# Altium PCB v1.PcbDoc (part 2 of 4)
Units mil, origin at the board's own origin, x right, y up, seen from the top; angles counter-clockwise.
Board outline 3043 x 5109 mil, 2 copper layers (Top Layer, Bottom Layer), stack 62 mil thick; 379 components, 219 nets, 963 pads, 1099 vias.
Unrouted connection lines stored in the file: 1.
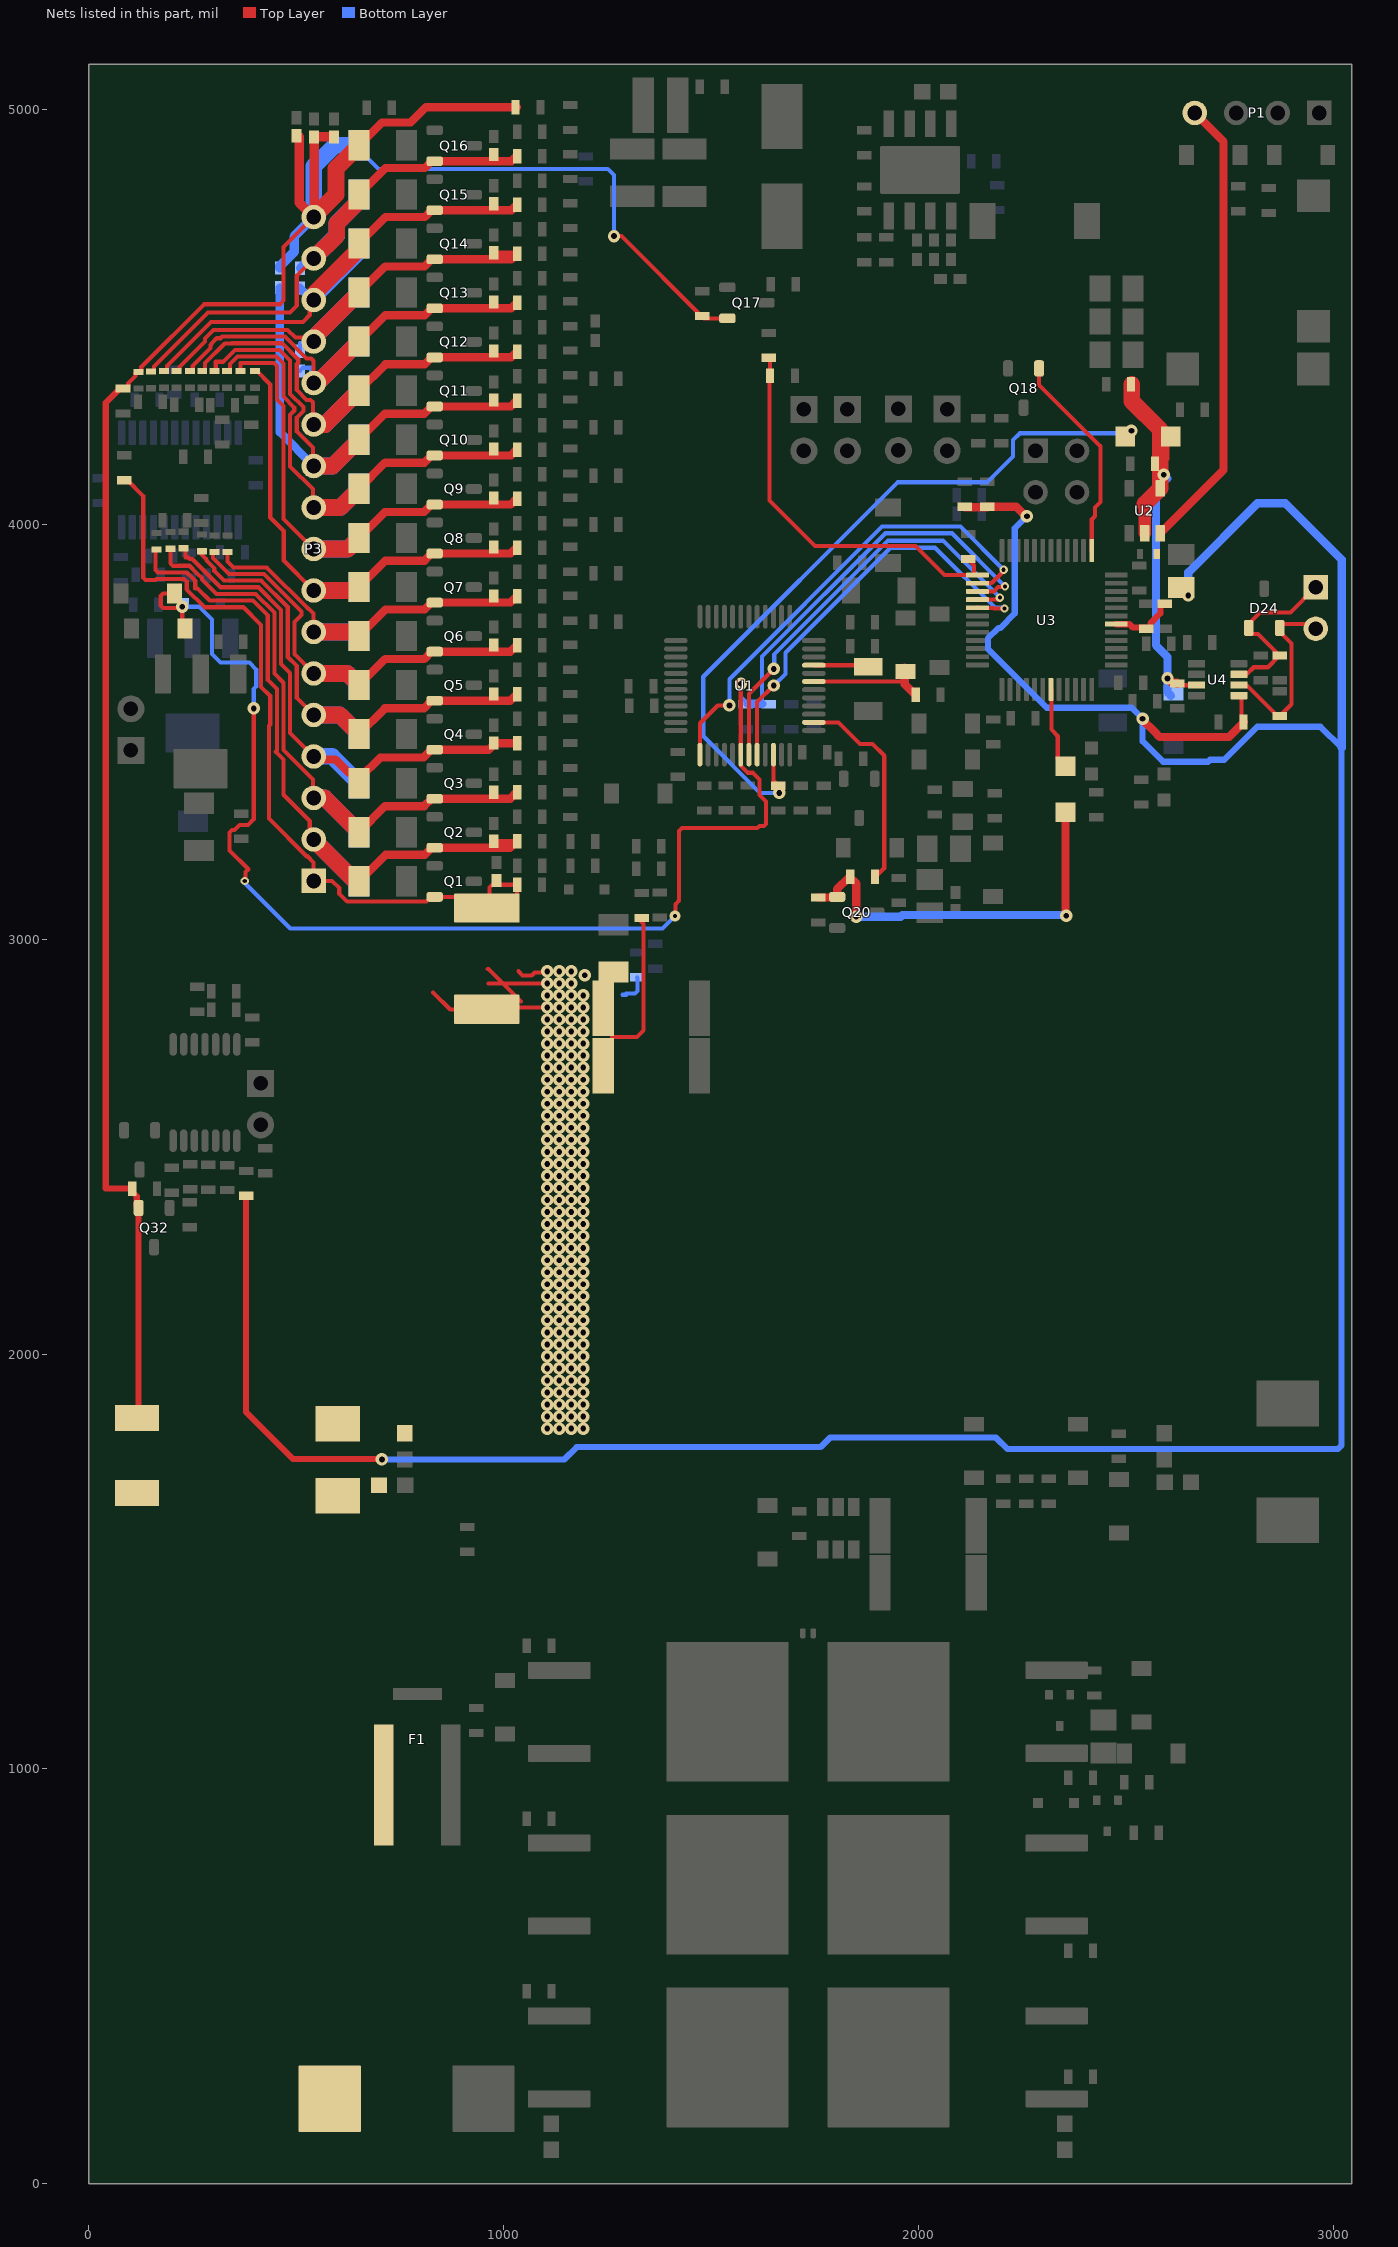
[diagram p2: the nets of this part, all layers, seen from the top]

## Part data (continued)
C34: library part CMP-0007444-4, "CAP, CERM, 0.022 uF, 50 V, +/- 10%, X7R, 0603", Cap_Case=0603, Manufacturer=MuRata, Supplier Part Number 1=490-1517-1-ND, TempCo=X7R, Tolerance_%=10%, Value1=Unknown, Value2=50V, ValueDisplayed=0.022uF
C36: library part CMP-0008710-2, "CAP, CERM, 1 uF, 100 V, +/- 10%, X7R, 1206", Cap_Case=1206_180, Manufacturer=TDK, Supplier Part Number 1=445-4467-1-ND, TempCo=X7R, Tolerance_%=10%, Value1="0.004575 ohm", Value2=100V, ValueDisplayed=1uF
C38: library part CMP-0007173-4, "CAP, CERM, 1000 pF, 50 V, +/- 5%, C0G/NP0, 0603", Cap_Case=0603, Manufacturer=MuRata, Supplier Part Number 1=490-1451-1-ND, TempCo=C0G/NP0, Tolerance_%=5%, Value1=Unknown, Value2=50V, ValueDisplayed=1000pF
C40: library part CMP-0008510-2, "CAP, CERM, 0.47 uF, 25 V, +/- 10%, X7R, 1206", Cap_Case=1206, Manufacturer=AVX, Supplier Part Number 1=478-1563-1-ND, TempCo=X7R, Tolerance_%=10%, Value1="0.018 ohm", Value2=25V, ValueDisplayed=0.47uF
C41: library part CMP-0007995-2, "CAP, CERM, 10 uF, 16 V, +/- 10%, X7R, 0805", Cap_Case=0805, Manufacturer="Samsung Electro-Mechanics", TempCo=X7R, Tolerance_%=10%, Value1=Unknown, Value2=16V, ValueDisplayed=10uF
C47 C48: library part CMP-0009135-2, "CAP, CERM, 4.7 uF, 100 V, +/- 10%, X7S, 1210", Cap_Case=1210, Manufacturer=TDK, Supplier Part Number 1=445-8912-1-ND, TempCo=X7S, Tolerance_%=10%, Value1=Unknown, Value2=100V, ValueDisplayed=4.7uF
C49 C58 C59 C60 C61 C62 C63: "CAP, CERM, 0.1 µF, 100 V,+/- 10%, X7R, 0603", Cap_Case=0603, Manufacturer=MuRata, Supplier Part Number 1=490-3285-1-ND, TempCo=X7R, Tolerance_%=10, Value2=100V, ValueDisplayed=0.1µF
C50: library part UUX2A4R7MCL1GS, "CAP, AL, 10 µF, 100 V, +/- 20%, SMD", Cap_Case=8x6.2mm, Manufacturer=Nichicon, Supplier Part Number 1=493-6282-1-ND, Tolerance_%=20, Value2=100V, ValueDisplayed=10µF
C51: library part CMP-0007224-4, "CAP, CERM, 56 pF, 50 V, +/- 5%, C0G/NP0, 0603", Cap_Case=0603, Manufacturer=MuRata, Supplier Part Number 1=490-1421-1-ND, TempCo=C0G/NP0, Tolerance_%=5%, Value1=Unknown, Value2=50V, ValueDisplayed=56pF
C52: library part CMP-0006683-2, "CAP, CERM, 2200 pF, 50 V, +/- 10%, X7R, 0402", Cap_Case=0402, Manufacturer=MuRata, Supplier Part Number 1=490-1305-1-ND, TempCo=X7R, Tolerance_%=10%, Value1=Unknown, Value2=50V, ValueDisplayed=2200pF
C53: library part CMP-0007171-4, "CAP, CERM, 100 pF, 50 V, +/- 5%, C0G/NP0, 0603", Cap_Case=0603, Manufacturer=MuRata, Supplier Part Number 1=490-1427-1-ND, TempCo=C0G/NP0, Tolerance_%=5%, Value1=Unknown, Value2=50V, ValueDisplayed=100pF
C54: library part CMP-0006678-2, "CAP, CERM, 1500 pF, 50 V, +/- 10%, X7R, 0402", Cap_Case=0402, Manufacturer=MuRata, Supplier Part Number 1=490-3245-1-ND, TempCo=X7R, Tolerance_%=10%, Value1=Unknown, Value2=50V, ValueDisplayed=1500pF
C55 C56 C57: library part CMP-0008334-2, "CAP, CERM, 4.7 uF, 16 V, +/- 10%, X7R, 0805", Cap_Case=0805, Manufacturer=MuRata, Supplier Part Number 1=490-4522-1-ND, TempCo=X7R, Tolerance_%=10%, Value1="0.006 ohm", Value2=16V, ValueDisplayed=4.7uF
C64 C65 C66 C67 C68 C69 C70 C71 C72 C73 C74 C75 C76 C77 C78 C79: library part CMP-0006837-2, "CAP, CERM, 0.1 uF, 50 V, +/- 10%, X7R, 0603", Cap_Case=0603, Manufacturer="Wurth Elektronik", TempCo=X7R, Tolerance_%=10%, Value1=Unknown, Value2=50V, ValueDisplayed=0.1uF
C80: library part CMP-0064935-2, "CAP, CERM, 0.1 uF, 100 V,+/- 10%, X7R, AEC-Q200 Grade 1, 0603", Cap_Case=0603, Manufacturer=MuRata, Supplier Part Number 1=490-13420-1-ND, TempCo=X7R, Tolerance_%=10%, Value1=Unknown, Value2=100V, ValueDisplayed=0.1uF
C85: library part CMP-0007152-2, "CAP, CERM, 1 uF, 10 V, +/- 10%, X6S, 0603", Cap_Case=0603, Manufacturer=MuRata, Supplier Part Number 1=GRM185C81A105KE36D-ND, TempCo=X6S, Tolerance_%=10%, Value1=Unknown, Value2=10V, ValueDisplayed=1uF
C87: library part CMP-0006563-2, "CAP, CERM, 1 uF, 10 V, +/- 10%, X5R, 0402", Cap_Case=0402, Manufacturer=MuRata, Supplier Part Number 1=490-3890-1-ND, TempCo=X5R, Tolerance_%=10%, Value1=Unknown, Value2=10V, ValueDisplayed=1uF
D1 D2 D3 D4 D5 D6 D7 D8 D12 D13 D14 D15 D16 D17 D18 D19: library part CMP-0005900-4, "Diode, Zener, 5.6 V, 300 mW, SOD-523", Manufacturer="Diodes Inc.", Power_W=300mW, Value1=0.3W
D9: library part CMP-0028447-2, "Diode, Schottky, 30 V, 0.2 A, SOD-323", Manufacturer="Diodes Inc.", Value1=0.2A, Value2=1V
D10 D22 D23: library part CMP-0005782-3, "Diode, Zener, 3.6 V, 500 mW, SOD-123", Manufacturer="ON Semiconductor", Power_W=500mW, Value1=0.5W
D11 D20 D29 D36: library part CMP-0076979-3, "Diode, Switching, 100 V, 0.25 A, SOD-523", Manufacturer=Nexperia, Value1=0.25A, Value2=1.25V
D21: library part CMP-0005787-3, "Diode, Zener, 5.6 V, 500 mW, SOD-123", Manufacturer="ON Semiconductor", Power_W=500mW, Value1=0.5W
D24: library part CMP-0078391-3, "Diode, TVS, Bi, 32 V, 66 Vc, AEC-Q101, SOT-23", Manufacturer="ON Semiconductor", Value1=350W
D25 D26: library part CMP-0002947-3, "LED, Red, SMD", Color=Red, Manufacturer="Wurth Elektronik", Power_TotalModule=72mW, Value1=0.072W, Value2=2V
D27 D28: library part CMP-0077033-2, "Diode, Schottky, 20 V, 1 A, SOD-123F", Manufacturer=Nexperia, Value1=1A, Value2=0.43V
D30: library part CMP-0005584-3, "Diode, TVS, Uni, 60 V, 96.8 Vc, SMB", Manufacturer="Diodes Inc.", Value1=600W
D31 D33 D38 D40: library part CMP-0005754-4, "Diode, Zener, 16 V, 500 mW, SOD-123", Manufacturer="Diodes Inc.", Power_W=500mW, Value1=0.5W
D32 D39 D41: library part MMSZ5263BT1G, "Diode, Zener, 75V, 500 mW, AEC-Q101, SOD-123", Manufacturer="ON Semiconductor", Power_W=0.5, Supplier Part Number 1=MMSZ5263BT1GOSCT-ND, Value1=0.5W
D34: library part CMP-0005738-4, "Diode, Zener, 56 V, 500 mW, AEC-Q101, SOD-123", Manufacturer="ON Semiconductor", Power_W=500mW, Value1=0.5W
D35 D42 D43 D44 D45 D48 D49: library part CMP-0028450-2, "Diode, Schottky, 100 V, 0.15 A, SOD-123", Manufacturer="Diodes Inc.", Value1=0.15A, Value2=0.6V
D37: library part CMP-0005865-3, "Diode, Zener, 5.1 V, 200 mW, SOD-323", Manufacturer="Diodes Inc.", Power_W=200mW, Value1=0.2W
D46: library part CMP-0029041-2, "Diode, Ultrafast, 200 V, 3 A, SMC", Manufacturer=Vishay-Semiconductor, Value1=3A, Value2=0.9V
D47: library part CMP-0005863-2, "Diode, Zener, 4.7 V, 250 mW, SOD-323", Manufacturer="Central Semiconductor", Power_W=250mW, Value1=0.25W
F1: library part SFK-5030, Irating_A=30, Manufacturer=POLYTRONICS
F2: library part 0678L9150-02, "Fuse, 30 A, 250 VAC, 72 VDC, SMD", Irating_A=15, Manufacturer="Bel Fuse", Supplier Part Number 1=507-2062-1-ND
L1: library part CMP-0064154-1, "Inductor, Shielded, 1 uH, 2.7 A, 0.039 ohm, SMD", Manufacturer="Wurth Elektronik", Supplier Part Number 1=732-4863-1-ND, Value1="0.039 ohm", Value2=2.7A, ValueDisplayed=1uH
L2: library part CMP-0064631-2, "Inductor, Shielded Drum Core, Metal Composite, 68 uH, 0.87 A, 0.239 ohm, SMD", Manufacturer="Wurth Elektronik", Supplier Part Number 1=732-1201-1-ND, Value1="0.239 ohm", Value2=0.87A, ValueDisplayed=68uH
L3 L4 L5 L6 L7 L8: library part CMP-0003196-2, "Ferrite Bead, 600 ohm @ 100 MHz, 0.2 A, 0603", Manufacturer="Wurth Elektronik", Supplier Part Number 1=732-1583-1-ND, Value1="0.45 ohm", Value2=0.2A, ValueDisplayed="600 ohm"
P1: "Header, 4-Pin"
P2: "Header, 2-Pin, Dual row"
P3: "Header, 17-Pin"
P4: "Header, 2-Pin"
Q1 Q2 Q3 Q4 Q5 Q6 Q7 Q8 Q9 Q10 Q11 Q12 Q13 Q14 Q15 Q16: library part CMP-0000211-1, "MOSFET, N-CH, 20 V, 2.8 A, AEC-Q101, SOT-23", Alternate Manufacturer=None, Manufacturer="Diodes Inc.", Supplier Part Number 1=DMG2302UK-7DICT-ND, Value1=0, Value2="1.4 nC"
Q17 Q32: library part CMP-0000158-3, "MOSFET, P-CH, -100 V, -0.6 A, SOT-23", Alternate Manufacturer=None, Manufacturer="Diodes Inc.", Value2="3.5 nC"
Q18 Q33: library part CMP-0000947-2, "MOSFET, N-CH, 100 V, 0.17 A, SOT-23", Alternate Manufacturer=None, Manufacturer="Fairchild Semiconductor", Supplier Part Number 1=BSS123NCT-ND, Value1=1, Value2="1.8 nC"
Q19: library part CMP-0000478-2, "Transistor, NPN, 100 V, 3 A, AEC-Q101, SOT-23", Manufacturer="Diodes Inc.", Supplier Part Number 1=ZXTN25100BFHCT-ND, Value1="3 A", Value2=300
Q20: library part CMP-0000971-2, "MOSFET, N-CH, 100 V, 1.4 A, SOT-23", Alternate Manufacturer=None, Manufacturer="Diodes Inc.", Supplier Part Number 1=DMN10H220L-7DICT-ND, Value1=0.2, Value2="4.1 nC"
Q21 Q22 Q23 Q25 Q26 Q27: library part CMP-0000966-3, "MOSFET, N-CH, 100 V, 200 A, KTT0002A (TO-263-2)", Alternate Manufacturer=None, Manufacturer="Texas Instruments", Supplier Part Number 1=296-41136-1-ND, Value2="118 nC"
Q24: library part CMP-0000049-3, "MOSFET, P-CH, -80 V, -2.1 A, SSOT-6", Alternate Manufacturer=None, Manufacturer="Fairchild Semiconductor", Value1=0.23, Value2="14 nC"
Q28: library part CMP-0000035-3, "MOSFET, P-CH, -20 V, -0.82 A, SOT-323", Alternate Manufacturer=None, Manufacturer="Diodes Inc.", Value1=0.7, Value2="0.622 nC"
Q29: library part CMP-0000776-1, "MOSFET, N-CH, 60 V, 0.115 A, SOT-323", Alternate Manufacturer=None, Manufacturer="Diodes Inc.", Supplier Part Number 1=2N7002W-FDICT-ND, Value1=7
Q30 Q31: library part CMP-0000992-1, "MOSFET, N-CH, 100 V, 3.3 A, SOT-223", Alternate Manufacturer=None, Manufacturer="Fairchild Semiconductor", Supplier Part Number 1=FDT86113LZCT-ND, Value1=0.14, Value2="4.1 nC"
R1 R2 R3 R4 R5 R6 R7 R8 R9 R10 R11 R12 R13 R14 R15 R16 R36 R37 R38 R39 R40 R41 R42 R43 R44 R45 R73 R74 R75 R76 R77 R78: library part CMP-0017186-3, "RES, 80.6, 1%, 0.25 W, AEC-Q200 Grade 0, 1206", Manufacturer=Vishay-Dale, Power_W=250mW, Supplier Part Number 1=541-80.6FCT-ND, TempCo="100 ppm/C", Tolerance_%=1%, Value2=0.25W, Value_Code=80R6, ValueDisplayed=80.6
R17 R19 R21 R23 R25 R27 R29 R31 R33 R52 R54 R56 R58 R60 R61 R80 R82 R87 R88 R89 R90 R95 R100 R101 R102 R107 R108 R115 R131 R165 R166: library part CMP-0021991-4, "RES, 100, 1%, 0.1 W, AEC-Q200 Grade 0, 0603", Manufacturer=Vishay-Dale, Power_W=100mW, Supplier Part Number 1=541-100HCT-ND, TempCo="100 ppm/C", Tolerance_%=1%, Value2=0.1W, Value_Code=100R, ValueDisplayed=100
R18 R20 R22 R24 R26 R28 R30 R32 R51 R53 R55 R57 R59 R71 R79 R81 R83 R91 R92 R103 R104 R137 R173 R174 R175: library part CMP-0025701-4, "RES, 10 k, 5%, 0.1 W, AEC-Q200 Grade 0, 0603", Manufacturer=Vishay-Dale, Power_W=100mW, Supplier Part Number 1=541-10KGCT-ND, TempCo="200 ppm/C", Tolerance_%=5%, Value2=0.1W, Value_Code=10k0, ValueDisplayed=10k
R34 R46 R47 R72 R117: library part CMP-0026822-3, "RES, 0, 5%, 0.063 W, AEC-Q200 Grade 0, 0402", Manufacturer=Vishay-Dale, Power_W=63mW, Supplier Part Number 1=541-0.0JCT-ND, TempCo="200 ppm/C", Tolerance_%=5%, Value2=0.063W, Value_Code=0000, ValueDisplayed=0
R35 R48 R49 R50 R62 R63 R64 R65 R66 R67 R68 R69 R70 R122: library part CMP-0025697-4, "RES, 0, 5%, 0.1 W, AEC-Q200 Grade 0, 0603", Manufacturer=Vishay-Dale, Power_W=100mW, Supplier Part Number 1=541-0.0GCT-ND, TempCo="200 ppm/C", Tolerance_%=5%, Value2=0.1W, Value_Code=0000, ValueDisplayed=0
R84: library part CMP-0025754-2, "RES, 20, 5%, 0.1 W, 0603", Manufacturer=Vishay-Dale, Power_W=100mW, Supplier Part Number 1=541-20GCT-ND, TempCo="200 ppm/C", Tolerance_%=5%, Value2=0.1W, Value_Code=20R0, ValueDisplayed=20
R85: library part CMP-0024664-3, "RES, 13.3 k, 0.5%, 0.1 W, 0603", Manufacturer="Yageo America", Power_W=100mW, TempCo="50 ppm/C", Tolerance_%=0.5%, Value2=0.1W, Value_Code=13k3, ValueDisplayed=13.3k
R86: library part CMP-0025495-3, "RES, 665 k, 0.5%, 0.1 W, 0603", Manufacturer="Yageo America", Power_W=100mW, TempCo="50 ppm/C", Tolerance_%=0.5%, Value2=0.1W, Value_Code=665k
R93 R168: library part CMP-0025801-4, "RES, 3.3 M, 5%, 0.1 W, AEC-Q200 Grade 0, 0603", Manufacturer=Vishay-Dale, Power_W=100mW, Supplier Part Number 1=541-3.3MGCT-ND, TempCo="200 ppm/C", Tolerance_%=5%, Value2=0.1W, Value_Code=3M30, ValueDisplayed=3.3M
R94 R127 R167: library part CMP-0025736-4, "RES, 1.0 M, 5%, 0.1 W, AEC-Q200 Grade 0, 0603", Manufacturer=Vishay-Dale, Power_W=100mW, Supplier Part Number 1=541-1.0MGCT-ND, TempCo="200 ppm/C", Tolerance_%=5%, Value2=0.1W, Value_Code=1M00, ValueDisplayed=1.0M
R96: library part CMP-0022942-5, "RES, 249, 1%, 0.1 W, 0603", Manufacturer=Yageo, Power_W=100mW, Supplier Part Number 1=311-249HRCT-ND, TempCo="100 ppm/C", Tolerance_%=1%, Value2=0.1W, Value_Code=249R, ValueDisplayed=249
R97: library part CMP-0021998-4, "RES, 10.0 k, 1%, 0.1 W, AEC-Q200 Grade 0, 0603", Manufacturer=Vishay-Dale, Power_W=100mW, Supplier Part Number 1=541-10.0KHCT-ND, TempCo="100 ppm/C", Tolerance_%=1%, Value2=0.1W, Value_Code=10k0, ValueDisplayed=10.0k
R98: library part CMP-0023133-5, "RES, 47.0 k, 1%, 0.1 W, 0603", Manufacturer=Yageo, Power_W=100mW, Supplier Part Number 1=311-47.0KHRCT-ND, TempCo="100 ppm/C", Tolerance_%=1%, Value2=0.1W, Value_Code=47k0, ValueDisplayed=47.0k
R99: library part CMP-0023630-3, "RES, 100 k, 0.1%, 0.1 W, 0603", Manufacturer="Yageo America", Power_W=100mW, Supplier Part Number 1=603-RT0603BRD07100KL, TempCo="25 ppm/C", Tolerance_%=0.1%, Value2=0.1W, Value_Code=100k
R105 R106: library part CMP-0023213-5, "RES, 60.4, 1%, 0.1 W, 0603", Manufacturer=Yageo, Power_W=100mW, Supplier Part Number 1=311-60.4HRCT-ND, TempCo="100 ppm/C", Tolerance_%=1%, Value2=0.1W, Value_Code=60R4, ValueDisplayed=60.4
R109 R110: library part CMP-0023129-5, "RES, 470, 1%, 0.1 W, 0603", Manufacturer=Yageo, Power_W=100mW, Supplier Part Number 1=311-470HRCT-ND, TempCo="100 ppm/C", Tolerance_%=1%, Value2=0.1W, Value_Code=470R, ValueDisplayed=470
R111: library part CMP-0018756-3, "RES, 0, 5%, 0.25 W, 1206", Manufacturer=Rohm, Power_W=250mW, Supplier Part Number 1=RHM0.0ECT-ND, TempCo="200 ppm/C", Tolerance_%=5%, Value2=0.25W, Value_Code=0000, ValueDisplayed=0
R112 R113: library part CMP-0015756-2, "RES, 0.002, 1%, 2 W, 2512", Manufacturer="Stackpole Electronics Inc", Power_W=2W, Supplier Part Number 1=CSNL2512FT2L00CT-ND, TempCo="50 ppm/C", Tolerance_%=1%, Value_Code=2L000, ValueDisplayed=0.002
R114 R140: library part CMP-0025830-4, "RES, 5.1 k, 5%, 0.1 W, AEC-Q200 Grade 0, 0603", Manufacturer=Vishay-Dale, Power_W=100mW, Supplier Part Number 1=541-5.1KGCT-ND, TempCo="200 ppm/C", Tolerance_%=5%, Value2=0.1W, Value_Code=5k10, ValueDisplayed=5.1k
R116: library part CMP-0022620-4, "RES, 82.5 k, 1%, 0.1 W, AEC-Q200 Grade 0, 0603", Manufacturer=Vishay-Dale, Power_W=100mW, Supplier Part Number 1=541-82.5KHCT-ND, TempCo="100 ppm/C", Tolerance_%=1%, Value2=0.1W, Value_Code=82k5, ValueDisplayed=82.5k
R118: library part CMP-0023140-4, "RES, 499 k, 1%, 0.1 W, 0603", Manufacturer=Yageo, Power_W=100mW, Supplier Part Number 1=311-499KHRCT-ND, TempCo="100 ppm/C", Tolerance_%=1%, Value2=0.1W, Value_Code=499k
R119: library part CRCW0402523KFKED, "RES, 523 k, 1%, 0.063 W, 0402", Manufacturer=Yageo, Power_W=0.063, Supplier Part Number 1=541-523KLCT-ND, TempCo="100 ppm/C", Tolerance_%=1, Value1=1%, Value2=0.063W, Value_Code=523k
R120: library part CMP-0022540-4, "RES, 63.4 k, 1%, 0.1 W, AEC-Q200 Grade 0, 0603", Manufacturer=Vishay-Dale, Power_W=100mW, Supplier Part Number 1=541-63.4KHCT-ND, TempCo="100 ppm/C", Tolerance_%=1%, Value2=0.1W, Value_Code=63k4, ValueDisplayed=63.4k
R121: library part CMP-0022200-4, "RES, 200 k, 1%, 0.1 W, AEC-Q200 Grade 0, 0603", Manufacturer=Vishay-Dale, Power_W=100mW, Supplier Part Number 1=541-200KHCT-ND, TempCo="100 ppm/C", Tolerance_%=1%, Value2=0.1W, Value_Code=200k
R123: library part CMP-0022201-5, "RES, 200, 1%, 0.1 W, AEC-Q200 Grade 0, 0603", Manufacturer=Vishay-Dale, Power_W=100mW, Supplier Part Number 1=541-200HCT-ND, TempCo="100 ppm/C", Tolerance_%=1%, Value2=0.1W, Value_Code=200R, ValueDisplayed=200
R124: library part CMP-0017628-3, "RES, 499, 1%, 0.25 W, AEC-Q200 Grade 0, 1206", Manufacturer=Panasonic, Power_W=250mW, Supplier Part Number 1=P499FCT-ND, TempCo="100 ppm/C", Tolerance_%=1%, Value2=0.25W, Value_Code=499R, ValueDisplayed=499
R125 R132 R138: library part CMP-0025702-4, "RES, 10 M, 5%, 0.1 W, AEC-Q200 Grade 0, 0603", Manufacturer=Vishay-Dale, Power_W=100mW, Supplier Part Number 1=541-10MGCT-ND, TempCo="200 ppm/C", Tolerance_%=5%, Value2=0.1W, Value_Code=10M0, ValueDisplayed=10M
R126 R139 R141: library part CMP-0024283-3, "RES, 49.9 k, 0.1%, 0.1 W, 0603", Manufacturer="Yageo America", Power_W=100mW, TempCo="25 ppm/C", Tolerance_%=0.1%, Value2=0.1W, Value_Code=49k9, ValueDisplayed=49.9k
R128 R129: library part CRCW2512604RFKEG, "RES SMD 510 OHM 5% 1W 2512", Manufacturer=Yageo, Power_W=1, Supplier Part Number 1=541-604AFCT-ND, TempCo="100 ppm/C", Value1=5%, Value2=1W, Value_Code=510R, ValueDisplayed=510
R130: library part CRCW080556K0JNEA, "RES, 56 k, 5%, 0.125 W, 0805", Manufacturer=Yageo, Power_W=0.125, Supplier Part Number 1=541-56KACT-ND, TempCo="200 ppm/C", Tolerance_%=5, Value1=5%, Value2=0.125W, Value_Code=56k0, ValueDisplayed=56k
R133 R134 R135: library part CMP-0021317-3, "RES, 511, 1%, 0.125 W, AEC-Q200 Grade 0, 0805", Manufacturer=Vishay-Dale, Power_W=125mW, Supplier Part Number 1=541-511CCT-ND, TempCo="100 ppm/C", Tolerance_%=1%, Value2=0.125W, Value_Code=511R, ValueDisplayed=511
R136: library part CMP-0022481-5, "RES, 511, 1%, 0.1 W, AEC-Q200 Grade 0, 0603", Manufacturer=Vishay-Dale, Power_W=100mW, Supplier Part Number 1=541-511HCT-ND, TempCo="100 ppm/C", Tolerance_%=1%, Value2=0.1W, Value_Code=511R, ValueDisplayed=511
R142 R143: library part CMP-0025753-4, "RES, 20 k, 5%, 0.1 W, AEC-Q200 Grade 0, 0603", Manufacturer=Vishay-Dale, Power_W=100mW, Supplier Part Number 1=541-20KGCT-ND, TempCo="200 ppm/C", Tolerance_%=5%, Value2=0.1W, Value_Code=20k0, ValueDisplayed=20k
R144 R145 R146 R147 R148 R149 R150 R151 R152 R153 R154 R155 R156 R157 R158 R159: library part CMP-0078193-1, "RES, 1.0 k, 5%, 0.1 W, AEC-Q200 Grade 0, 0402", Manufacturer=Panasonic, Power_W=100mW, Supplier Part Number 1=P1.0KJCT-ND, TempCo="200 ppm/C", Tolerance_%=5%, Value2=0.1W, Value_Code=1k00, ValueDisplayed=1.0k
R160: library part CMP-0025781-4, "RES, 300, 5%, 0.1 W, AEC-Q200 Grade 0, 0603", Manufacturer=Vishay-Dale, Power_W=100mW, Supplier Part Number 1=541-300GCT-ND, TempCo="200 ppm/C", Tolerance_%=5%, Value2=0.1W, Value_Code=300R, ValueDisplayed=300
R161 R162 R178 R180: library part CMP-0025700-4, "RES, 100, 5%, 0.1 W, AEC-Q200 Grade 0, 0603", Manufacturer=Vishay-Dale, Power_W=100mW, Supplier Part Number 1=541-100GCT-ND, TempCo="200 ppm/C", Tolerance_%=5%, Value2=0.1W, Value_Code=100R, ValueDisplayed=100
R163 R164: library part CMP-0016578-1, "RES, 10.0 k, 1%, 0.5 W, 1206", Manufacturer=Vishay-Dale, Power_W=500mW, Supplier Part Number 1=541-10.0KUCT-ND, TempCo="100 ppm/C", Tolerance_%=1%, Value2=0.5W, Value_Code=10k0, ValueDisplayed=10.0k
R169 R170: library part CMP-0024305-2, "RES, 505 k, 0.1%, 0.1 W, 0603", Manufacturer="Yageo America", Power_W=100mW, TempCo="25 ppm/C", Tolerance_%=0.1%, Value2=0.1W, Value_Code=505k
R171: library part CMP-0023800-3, "RES, 16.5 k, 0.1%, 0.1 W, 0603", Manufacturer="Yageo America", Power_W=100mW, TempCo="25 ppm/C", Tolerance_%=0.1%, Value2=0.1W, Value_Code=16k5, ValueDisplayed=16.5k
R172: library part CMP-0023135-5, "RES, 47.0, 1%, 0.1 W, 0603", Manufacturer=Yageo, Power_W=100mW, Supplier Part Number 1=311-47.0HRCT-ND, TempCo="100 ppm/C", Tolerance_%=1%, Value2=0.1W, Value_Code=47R0, ValueDisplayed=47.0
R176: library part CMP-0016044-2, "RES, 0, 5%, 0.75 W, AEC-Q200 Grade 0, 2010", Manufacturer=Vishay-Dale, Power_W=750mW, Supplier Part Number 1=541-0.0WCT-ND, TempCo=ppm/C, Tolerance_%=5%, Value2=0.75W, Value_Code=0000, ValueDisplayed=0
R177: library part CMP-0025702-2, "RES, 10 M, 5%, 0.1 W, 0603", Manufacturer=Vishay-Dale, Power_W=100mW, Supplier Part Number 1=541-10MGCT-ND, TempCo="200 ppm/C", Tolerance_%=5%, Value2=0.1W, Value_Code=10M0, ValueDisplayed=10M
R179: library part CMP-0096746-1, "0 Ohms Jumper 1W Chip Resistor 2512 (6432 Metric) Moisture Resistant Thick Film", Digikey Part Number=13-RC2512FK-070RLCT-ND, Manufacturer=YAGEO, Max Current=10A, Mouser Part Number=603-RC2512FK-070RL, Operating Temperature Range="-55°C to +155°C", Power_W=1W
RT1 RT2 RT3 RT4: library part 103AT-2, "Thermistor NTC, 10.0k ohm, 1%, Disc, 5x8.4 mm", Manufacturer=Cantherm, Power_W=0.01, Supplier Part Number 1=954-103AT-2, Tolerance_%=1
RT5: library part CMP-0084566-1, "Thermistor, DEC0002A (X1SON-2)", Alternate Manufacturer="Texas Instruments", Alternate PartNumber=TMP6131DECT
RT6 RT7: library part CMP-0002341-2, "Thermistor NTC, 10.0k ohm, 1%, Disc, 5x8.4 mm", Manufacturer="SEMITEC Corporation", Power_W=10mW, Supplier Part Number 1=954-103AT-2, Tolerance_%=1%
S1 S2: library part CMP-0002210-1, "Switch, Tactile, SPST-NO, 0.05A, 12V, SMD", CurrentRating_mA=50A, Manufacturer="C&K Components", Supplier Part Number 1=CKN10388CT-ND
U1: library part CMP-0084230-1, "Multicell Battery Monitor and Protection Family, PFB0048A (TQFP-48)", Alternate Manufacturer="Texas Instruments", Alternate PartNumber=bq76952PFBT
U2: library part CMP-0035592-1, "Single Output LDO, 150 mA, Fixed 3.3 V Output, 2.5 to 24 V Input, with Ultra-Low IQ, 5-pin SOT-23 (DBV), -40 to 125 degC, Green (RoHS & no Sb/Br)", Manufacturer="Texas Instruments"
U3: library part CMP-0093961-1, "Mixed-Signal Microcontrollers with CAN-FD Interface ARM Cortex-M0+ 32bits 128KB Flash 32KB RAM LQFP48 AEC Q-200 Grade 1 80MHz", Frequency_Fixed=80MHz, Manufacturer="Texas Instruments", Max Supply Voltage=3.6V, Min Supply Voltage=1.62V, Operating Temperature Range="-40°C to +125°C"
U4: library part CMP-0089901-1, "Automotive High Speed CAN Transceiver", Manufacturer="Texas Instruments", Max Supply Voltage=5.5V, Min Supply Voltage=4.5V, Nominal Supply Current=5-180mA, Operating Temperature Range="-40°C to +150°C", PartNumber=TCAN1044VDDFR
U5: library part CMP-0861029-1, "100-V Input, 0.5-A Synchronous Buck DC/DC Converter with Ultra-low IQ, DDA0008E (HSOIC-8)", Alternate Manufacturer="Texas Instruments"
U6: library part CMP-0088789-1, "Voltage and Temperature Protection for 3-Series to 16-Series Cell Li-Ion Batteries with Internal Delay Timer", Manufacturer="Texas Instruments", Max Supply Voltage=85V, Min Supply Voltage=5V, Nominal Supply Current=1uA, Operating Temperature Range="-65°C to +150°C"
U7: library part CMP-0082026-1, "Multi-Chemistry Impedance Track Standalone Fuel Gauge", Alternate Manufacturer="Texas Instruments", Operating Temperature Range="-40 to 85 C"

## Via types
v1: diameter 30, hole 14, Top Layer to Bottom Layer, 1049 vias
v2: diameter 20, hole 10, Top Layer to Bottom Layer, 38 vias
v3: diameter 19.68, hole 7.87, Top Layer to Bottom Layer, tented both sides, 4 vias
v4: diameter 19.68, hole 7.87, Top Layer to Bottom Layer, 4 vias
v5: diameter 34, hole 16, Top Layer to Bottom Layer, 3 vias
v6: diameter 26, hole 10, Top Layer to Bottom Layer, 1 vias

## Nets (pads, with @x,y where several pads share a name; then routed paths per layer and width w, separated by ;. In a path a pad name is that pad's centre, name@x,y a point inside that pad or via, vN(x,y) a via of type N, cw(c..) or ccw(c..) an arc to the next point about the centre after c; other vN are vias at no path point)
3V3: C41.2 C43.2 C45.1 C87.1 P1.4 R98.2 R103.1 R104.1 R172.1 U2.3 U3.6 U4.5 | length 9143.7
  Top Layer w10: U4.5@2777.53,3586.29 2777.53,3529.72 C45.1@2783.91,3523.35
  Top Layer w12: v1(2260.41,4019.35) v1@2263.41,4019.35
  Top Layer w15: R172.1@378.59,2381.35 378.59,1860.32 491.91,1747 v1@704,1747 ; U3.6@2475.95,3759.33 2476.23,3759.06 2507.96,3759.06 2516.16,3750.85 2545.91,3750.85 C43.2@2548.41,3748.35 2555.91,3748.35 2558.41,3750.85 2558.41,3760.94 2582.41,3784.94 2582.41,3805.85 2584.91,3808.35 R98.2@2592.41,3808.35
  Top Layer w20: R104.1@2110.41,4040.85 R103.1@2165.41,4040.85 ; R103.1@2165.41,4042.35 2234.7,4042.35 2257.7,4019.35 v1(2260.41,4019.35) ; v1(2539.41,3531.35) 2539.41,3528.64 2566.27,3501.78 2566.27,3501.49 2580.41,3487.35 2747.91,3487.35 C45.1@2783.91,3523.35 ; U2.3@2581.81,3978.21 2734.41,4130.81 2734.41,4922 P1.4@2665.11,4991.3 ; C41.2@2633.41,3849.36 C41.2@2650.41,3832.36
  Bottom Layer w15: v1(706.07,1746.21) 1146.04,1746.21 1175.68,1775.85 1763,1775.85 1786,1798.85 2186.08,1798.85 2213.92,1771 3010.21,1771 3019,1779.79 3019,3461 2968,3512 2815.72,3512 2736.08,3432.37 2702.07,3432.37 2697.21,3427.5 2588.67,3427.5 2539.41,3476.76 v1(2539.41,3531.35) 2512.88,3557.85 2308.27,3557.85 2166.66,3699.46 2166.66,3724.74 2191.77,3749.85 2196.14,3749.85 2231.22,3784.93 2231.22,3990.16 v1(2260.41,4019.35)
  Bottom Layer w20: v1(2649.41,3828.36) 2649.41,3884.08 2815.68,4050.35 2883.65,4050.35 3019,3915 3019,3461
5V: C42.1 C44.1 D21.1 D27.1 R122.1 U2.2 U2.4 U4.3 | length 1120.3
  Top Layer w10: C44.1@2622.41,3611.35 2622.95,3611.88 U4.3@2667.29,3611.88
  Top Layer w20: 2581.81,4146.35 2593.91,4158.44 2593.91,4197.72 D27.1@2607.53,4211.35 ; v1(2599.41,3628.35) 2609.91,3617.84 C44.1@2622.41,3617.84 ; C44.1@2622.41,3615.37 C44.1@2622.41,3616.35
  Top Layer w30: U2.2@2544.41,3978.21 2544.41,4049.08
  Top Layer w40: R122.1@2512.91,4337.35 2512.91,4296.87 2581.81,4227.96 2581.81,4146.35 U2.4@2581.81,4086.48 2544.41,4049.08
  Bottom Layer w20: v1@2599.41,4110.35 v1(2590.41,4119.35) 2590.41,4116.64 2571.41,4097.64 2571.41,3708.05 2599.41,3680.05 v1(2599.41,3628.35) 2599.41,3594.81 D21.1@2607.41,3586.81
5V_AFE: C30.1 D27.2 U1.34 | length 1786.4
  Top Layer w10: U1.34@1649.65,3444.74 1649.65,3382.68 1663.82,3368.5 1663.82,3355.1 1661.06,3352.35 v1(1663.82,3352.35)
  Bottom Layer w10: v1(1663.82,3352.35) 1617.41,3352.35 1480.41,3489.35 1480.41,3632.35 1949.41,4101.35 2165.41,4101.35 2227.41,4163.35 2227.41,4203.35 2243.41,4219.35 2506.41,4219.35 v1(2512.41,4225.35)
ALERT: U1.25 U3.26 | length 1162.3
  Top Layer w10: U1.25@1472.48,3444.74 1472.48,3520.42 1515.41,3563.35 v1(1543.41,3563.35) ; U3.26@2141.3,3857.76 2142.21,3858.67 2175.73,3858.67 2197.41,3880.35 2197.41,3880.64 2204.41,3887.64 v2(2204.41,3890.35)
  Bottom Layer w10: v1(1543.41,3563.35) 1543.41,3626.35 1911.41,3994.35 2100.41,3994.35 v2(2204.41,3890.35)
BAT+: C59.1 D30.1 F1.3 F2.2 R176.1
BAT-: C58.2 C80.2 D1.2 D30.2 P3.1 Q1.2 R17.1 R88.1 R111.2 R112.1 R113.1 R166.1 R179.1 R179.2 | length 3063.3
  Top Layer w10: C80.2@85,4106 92.5,4106 130.69,4067.81 130.69,3871.86 136.54,3866 160.42,3866 162.43,3868.02 229.04,3868.02 235.48,3861.57 235.48,3843.21 278.58,3800.1 371.9,3800.1 415,3757 415,3607.88 436.88,3586 436.88,3517.03 434,3514.15 434,3290.44 524.62,3199.82 526.46,3199.82 541.41,3184.87 P3.1@541.41,3140.35 585.94,3140.35 603.32,3122.96 603.32,3109.31 622.29,3090.35 813.2,3090.35 824.8,3101.94 Q1.2@833.17,3101.94 944.33,3101.94 965,3081.28 965,3124.35 971.25,3130.6 975.19,3130.6 D1.2@982,3137.41 ; 829.17,2871.83 870.65,2830.35 R179.2@959,2830.35 ; R179.2@959,2830.95 963.39,2835.35 v1(1104.41,2835.35) ; R179.1@959,3075.05 R179.1@978,3075.05 ; 961,2927.72 962.97,2927.72 1041.2,2849.49 ; 963,2893.35 v1(1104.41,2893.35) ; R179.1@978,3074.41 R179.1@978,3075.05 ; R179.1@978,3078.35 R179.1@978,3075.05 ; D1.2@982,3137.81 988.81,3131 R17.1@1032,3131 1031.31,3130.31 1031.31,3105.48 1000.87,3075.05 R179.1@978,3075.05 ; R179.1@999.53,3055.35 R179.1@1028.41,3055.35 ; 1035.02,2922.67 1045.2,2912.49 1067.17,2912.49 1074.41,2919.73 1101.79,2919.73 v1(1104.41,2922.35) ; 1260.41,2764.35 1320.41,2764.35 1336.41,2780.35 1336.41,3036.35 R88.1@1321.91,3050.85
  Bottom Layer w10: 1286,2866 1295,2866 1294,2867 1294,2869 1316.14,2869 1322,2874.86 1322,2907 R166.1@1321,2908
  other v1: 1104.41,1820.35 1133.41,1820.35 1162.41,1820.35 1191.41,1820.35 1104.41,1849.35 1133.41,1849.35 1162.41,1849.35 1191.41,1849.35 1104.41,1878.35 1133.41,1878.35 1162.41,1878.35 1191.41,1878.35 1104.41,1907.35 1133.41,1907.35 1162.41,1907.35 1191.41,1907.35 1104.41,1936.35 1133.41,1936.35 1162.41,1936.35 1191.41,1936.35 1104.41,1965.35 1133.41,1965.35 1162.41,1965.35 1191.41,1965.35 1104.41,1994.35 1133.41,1994.35 1162.41,1994.35 1191.41,1994.35 1104.41,2023.35 1133.41,2023.35 1162.41,2023.35 1191.41,2023.35 1104.41,2052.35 1133.41,2052.35 1162.41,2052.35 1191.41,2052.35 1104.41,2081.35 1133.41,2081.35 1162.41,2081.35 1191.41,2081.35 1104.41,2110.35 1133.41,2110.35 1162.41,2110.35 1191.41,2110.35 1104.41,2139.35 1133.41,2139.35 1162.41,2139.35 1191.41,2139.35 1104.41,2168.35 1133.41,2168.35 1162.41,2168.35 1191.41,2168.35 1104.41,2197.35 1133.41,2197.35 1162.41,2197.35 1191.41,2197.35 1104.41,2226.35 1133.41,2226.35 1162.41,2226.35 1191.41,2226.35 1104.41,2255.35 1133.41,2255.35 1162.41,2255.35 1191.41,2255.35 1104.41,2284.35 1133.41,2284.35 1162.41,2284.35 1191.41,2284.35 1104.41,2313.35 1133.41,2313.35 1162.41,2313.35 1191.41,2313.35 1104.41,2342.35 1133.41,2342.35 1162.41,2342.35 1191.41,2342.35 1104.41,2371.35 1133.41,2371.35 1162.41,2371.35 1191.41,2371.35 1104.41,2400.35 1133.41,2400.35 1162.41,2400.35 1191.41,2400.35 1104.41,2429.35 1133.41,2429.35 1162.41,2429.35 1191.41,2429.35 1104.41,2458.35 1133.41,2458.35 1162.41,2458.35 1191.41,2458.35 1104.41,2487.35 1133.41,2487.35 1162.41,2487.35 1191.41,2487.35 1104.41,2516.35 1133.41,2516.35 1162.41,2516.35 1191.41,2516.35 1104.41,2545.35 1133.41,2545.35 1162.41,2545.35 1191.41,2545.35 1104.41,2574.35 1133.41,2574.35 1162.41,2574.35 1191.41,2574.35 1104.41,2603.35 1133.41,2603.35 1162.41,2603.35 1191.41,2603.35 1104.41,2632.35 1133.41,2632.35 1162.41,2632.35 1191.41,2632.35 1104.41,2661.35 1133.41,2661.35 1162.41,2661.35 1191.41,2661.35 1104.41,2690.35 1133.41,2690.35 1162.41,2690.35 1191.41,2690.35 1104.41,2719.35 1133.41,2719.35 1162.41,2719.35 1191.41,2719.35 1104.41,2748.35 1133.41,2748.35 1162.41,2748.35 1191.41,2748.35 1104.41,2777.35 1133.41,2777.35 1162.41,2777.35 1191.41,2777.35 1104.41,2806.35 1133.41,2806.35 1162.41,2806.35 1191.41,2806.35 1133.41,2835.35 1162.41,2835.35 1191.41,2835.35 1104.41,2864.35 1133.41,2864.35 1162.41,2864.35 1191.41,2864.35 1133.41,2893.35 1162.41,2893.35 1195,2913 1133.41,2922.35 1162.41,2922.35
BAT_ADC: C37.2 R85.2 R86.1 U3.25 | length 964.7
  Top Layer w10: R86.1@1638,4401 1641.41,4397.59 R85.2@1641.41,4357.85 ; R85.2@1639.91,4357.85 1639.91,4056.84 1749.41,3947.35 1991.91,3947.35 2061.81,3877.44 U3.25@2134.02,3877.44 ; C37.2@2119.41,3914.85 2133.11,3901.15 2133.11,3878.35 U3.25@2134.02,3877.44 ; U3.25@2141.3,3877.44 U3.25@2134.02,3877.44
BATS_EN: Q18.1 U3.13 | length 509.2
  Top Layer w10: Q18.1@2289.81,4375.59 2289.81,4335.94 2437.94,4187.82 2437.94,4053.93 2424.41,4040.4 2424.41,4019.35 2416.89,4011.83 U3.13@2416.89,3936.5
CANH: D24.1 P4.1 R106.1 U4.7 | length 438.1
  Top Layer w10: U4.7@2771.59,3638.14 2789.94,3638.14 2807.15,3655.35 2841.08,3655.35 R106.1@2869.41,3683.68 2817.74,3735.35 2801.41,3735.35 2795.01,3741.75 D24.1@2795.01,3750.1 2795.01,3759.94 2822.41,3787.35 2895.41,3787.35 P4.1@2956.41,3848.35 ; U4.7@2777.53,3637.47 U4.7@2784.23,3637.47
CANL: D24.2 P4.2 R105.2 U4.6 | length 456.2
  Top Layer w10: U4.6@2771.59,3612.55 2789.94,3612.55 2864.82,3537.68 R105.2@2869.41,3537.68 2897.91,3566.18 2897.91,3712.85 2871.57,3739.19 2871.57,3748.35 D24.2@2869.81,3750.1 ; U4.6@2777.53,3611.88 U4.6@2784.23,3611.88 ; D24.2@2872.41,3759.35 P4.2@2957.25,3759.35
Cell1: D2.2 P3.2 Q2.2 R1.1 R2.1 R19.1 R144.1 | length 1726.9
  Top Layer w10: R144.1@163,3939 162.5,3939 160,3936.5 160,3889.87 165.86,3884.02 235.66,3884.02 249.26,3870.42 256.08,3863.6 256.08,3845.24 261.87,3845.24 291,3816.1 395.2,3816.1 431,3780.3 431,3624.88 452.88,3603 452.88,3454.7 450,3451.81 469,3432.81 469,3348 532.13,3284.87 532.13,3249.63 P3.2@541.41,3240.35 ; D2.2@975.41,3235.89 1030.52,3235.89 R19.1@1030.91,3236.28
  Top Layer w20: R2.1@650.85,3139.35 714.85,3203.35 809.1,3203.35 825.9,3220.15 Q2.2@833.17,3220.15 1014.78,3220.15 R19.1@1030.52,3235.89
  Top Layer w40: P3.2@541.41,3240.35 R2.1@642.41,3139.35
  Bottom Layer w40: P3.2@541.41,3240.35 R1.1@642.41,3139.35
Cell2: D3.2 P3.3 Q3.2 R3.1 R4.1 R21.1 R145.1 | length 1529.7
  Top Layer w10: R145.1@197,3941 196.83,3940.83 196.83,3905.87 202.69,3900.02 242.29,3900.02 260.71,3881.6 272.08,3870.23 272.08,3867.1 307.07,3832.1 401.83,3832.1 447,3786.93 447,3639.88 468.88,3618 468.88,3455.56 539.57,3384.87 539.57,3342.19 P3.3@541.41,3340.35
  Top Layer w20: R4.1@650.85,3257.6 713.6,3320.35 807.9,3320.35 825.9,3338.35 Q3.2@833.17,3338.35 1015.04,3338.35 R21.1@1030.91,3354.22
  Top Layer w40: P3.3@541.41,3340.35 568.11,3340.35 R4.1@650.85,3257.6
  Bottom Layer w40: P3.3@541.41,3340.35 568.11,3340.35 R3.1@650.85,3257.6
Cell3: D4.2 P3.4 Q4.2 R5.1 R6.1 R23.1 R146.1 | length 1392
  Top Layer w10: R146.1@228,3942 230.02,3942 232.52,3939.5 232.52,3919.5 239.44,3919.5 242.93,3916.02 248.92,3916.02 316.83,3848.1 408.45,3848.1 463,3793.56 463,3662.88 484.88,3641 484.88,3496.87 P3.4@541.41,3440.35
  Top Layer w20: P3.4@541.41,3440.35 548.88,3432.87 593.84,3432.87 624.44,3402.28 635.26,3402.28 R6.1@650.85,3386.69 ; R6.1@650.85,3375.86 R6.1@650.85,3386.69 ; R23.1@1032.41,3472.15 R23.1@1032.41,3472.15 975.48,3472.22 D4.2@975.41,3472.29 975.41,3468.36 963.6,3456.55 Q4.2@833.17,3456.55 825.29,3456.55 806.61,3437.86 702.03,3437.86 R6.1@650.85,3386.69
  Bottom Layer w40: P3.4@541.41,3440.35 586.37,3440.35 R5.1@650.85,3375.86
Cell4: D5.2 P3.5 Q5.2 R7.1 R8.1 R25.1 R147.1 | length 1235.3
  Top Layer w10: R147.1@266.5,3932 283,3915.5 283,3912.32 302.08,3893.24 302.08,3887.03 325,3864.1 415.08,3864.1 479,3800.19 479,3680.13 500.88,3658.25 500.88,3580.87 P3.5@541.41,3540.35
  Top Layer w20: R8.1@650.85,3494.12 713.08,3556.35 807.5,3556.35 825.9,3574.74 Q5.2@833.17,3574.74 1015.57,3574.74 R25.1@1030.91,3590.09
  Top Layer w40: P3.5@541.41,3540.35 604.63,3540.35 R8.1@650.85,3494.12
  Bottom Layer w40: P3.5@541.41,3540.35 604.63,3540.35 R7.1@650.85,3494.12
Cell5: D6.2 P3.6 Q6.2 R9.1 R10.1 R27.1 R148.1 | length 1116.3
  Top Layer w10: R148.1@296.5,3930 299,3927.5 299,3918.94 337.84,3880.1 421.71,3880.1 512.26,3789.55 512.26,3781.26 495,3764 495,3686.76 P3.6@541.41,3640.35
  Top Layer w20: R10.1@650.85,3612.38 713.83,3675.35 808.3,3675.35 825.9,3692.94 Q6.2@833.17,3692.94 1015.83,3692.94 R27.1@1030.91,3708.02
  Top Layer w40: P3.6@541.41,3640.35 622.88,3640.35 R10.1@650.85,3612.38
  Bottom Layer w40: P3.6@541.41,3640.35 622.88,3640.35 R9.1@650.85,3612.38
Cell6: D7.2 P3.7 Q7.2 R11.1 R12.1 R29.1 R149.1 | length 945.8
  Top Layer w10: R149.1@333.69,3933 333.69,3910.41 348,3896.1 428.34,3896.1 527.44,3797 529.14,3797 541.27,3784.87 541.27,3740.49 P3.7@541.41,3740.35
  Top Layer w20: R12.1@660.57,3740.35 714.57,3794.35 809.1,3794.35 825.9,3811.15 Q7.2@833.17,3811.15 1016.1,3811.15 R29.1@1030.91,3825.96
  Top Layer w40: P3.7@541.41,3740.35 641.14,3740.35 R12.1@650.85,3730.63
  Bottom Layer w40: P3.7@541.41,3740.35 R11.1@641.14,3740.35
Cell7: D8.2 P3.8 Q8.2 R13.1 R14.1 R31.1 R150.1 | length 1223.2
  Top Layer w10: R150.1@400,4369 404.5,4369 436.88,4336.62 436.88,4016.17 469.51,3983.54 469.51,3912.24 P3.8@541.41,3840.35
  Top Layer w20: R13.1@650.85,3848.89 714.31,3912.35 808.9,3912.35 825.9,3929.35 Q8.2@833.17,3929.35 1016.36,3929.35 R31.1@1030.91,3943.89
  Top Layer w40: P3.8@541.41,3840.35 642.31,3840.35 R13.1@650.85,3848.89
  Bottom Layer w40: P3.8@541.41,3840.35 R14.1@642.31,3840.35
Cell8: D12.2 P3.9 Q9.2 R15.1 R16.1 R33.1 R151.1 | length 1248
  Top Layer w10: R151.1@365,4369 365,4388.35 445.59,4388.35 452.88,4381.05 452.88,4300.86 468.88,4284.86 468.88,4012.87 P3.9@541.41,3940.35
  Top Layer w20: R16.1@650.85,3967.15 713.05,4029.35 807.7,4029.35 825.9,4047.55 Q9.2@833.17,4047.55 1016.63,4047.55 R33.1@1030.91,4061.83
  Top Layer w40: P3.9@541.41,3940.35 624.05,3940.35 R16.1@650.85,3967.15
  Bottom Layer w40: P3.9@541.41,3940.35 624.05,3940.35 R15.1@650.85,3967.15
Cell9: D13.2 P3.10 Q10.2 R36.1 R37.1 R52.1 R152.1 | length 1226.7
  Top Layer w10: R152.1@333,4369 337.5,4369 340,4371.5 340,4385.97 358.37,4404.35 452.21,4404.35 468.88,4387.68 468.88,4307.49 494.6,4281.77 494.6,4273.48 484.88,4263.76 484.88,4139.56 539.57,4084.87 539.57,4042.19 P3.10@541.41,4040.35
  Top Layer w20: R37.1@650.85,4085.4 713.8,4148.35 808.5,4148.35 825.9,4165.74 Q10.2@833.17,4165.74 1016.89,4165.74 R52.1@1030.91,4179.77
  Top Layer w40: P3.10@541.41,4040.35 605.8,4040.35 R37.1@650.85,4085.4
  Bottom Layer w40: P3.10@541.41,4040.35 605.8,4040.35 R36.1@650.85,4085.4
Cell10: D14.2 P3.11 Q11.2 R38.1 R39.1 R47.2 R54.1 R153.1 | length 1670.7
  Top Layer w10: R153.1@303,4369 303.2,4369 305.7,4371.5 305.7,4391.5 322.9,4391.5 351.75,4420.35 458.84,4420.35 484.88,4394.3 484.88,4314.12 516.86,4282.14 516.86,4273.11 500.88,4257.13 500.88,4223.56 539.57,4184.87 539.57,4142.19 P3.11@541.41,4140.35
  Top Layer w20: R39.1@650.85,4203.66 713.54,4266.35 808.3,4266.35 825.9,4283.94 Q11.2@833.17,4283.94 1017.16,4283.94 R54.1@1030.91,4297.7
  Top Layer w40: P3.11@541.41,4140.35 587.54,4140.35 R39.1@650.85,4203.66
  Bottom Layer w20: R47.2@460,4570.76 460,4221.76 P3.11@541.41,4140.35
  Bottom Layer w40: P3.11@541.41,4140.35 587.54,4140.35 R38.1@650.85,4203.66
Cell11: D15.2 P3.12 Q12.2 R40.1 R41.1 R56.1 R154.1 | length 1171.2
  Top Layer w10: R154.1@273,4369 277.5,4369 280,4371.5 280,4388.43 327.31,4435.74 344.51,4435.74 345.12,4436.35 465.47,4436.35 504.3,4397.52 504.3,4389.23 500.88,4385.82 500.88,4323.56 524.62,4299.82 533.71,4299.82 539.57,4293.96 539.57,4242.19 P3.12@541.41,4240.35
  Top Layer w20: R41.1@650.85,4321.92 714.28,4385.35 809.1,4385.35 825.9,4402.15 Q12.2@833.17,4402.15 1017.42,4402.15 R56.1@1030.91,4415.64
  Top Layer w40: P3.12@541.41,4240.35 569.28,4240.35 R41.1@650.85,4321.92
  Bottom Layer w40: P3.12@541.41,4240.35 569.28,4240.35 R40.1@650.85,4321.92
Cell12: D16.2 P3.13 Q13.2 R34.1 R42.1 R43.1 R58.1 R155.1 | length 1211.6
  Top Layer w10: R155.1@243,4369 247.5,4369 250,4371.5 250,4381.06 293.29,4424.35 293.29,4431.72 295.29,4433.72 295.29,4435.64 307.83,4448.17 317.12,4448.17 321.29,4452.35 472.09,4452.35 524.62,4399.82 535.55,4399.82 541.41,4393.96 P3.13@541.41,4340.35
  Top Layer w20: R43.1@650.85,4440.18 714.02,4503.35 808.9,4503.35 825.9,4520.35 Q13.2@833.17,4520.35 1017.69,4520.35 R58.1@1030.91,4533.57
  Top Layer w40: P3.13@541.41,4340.35 551.02,4340.35 R43.1@650.85,4440.18
  Bottom Layer w10: R34.1@508.41,4369.72 508.41,4370.19 515.22,4377 535.55,4377 535.55,4346.2 P3.13@541.41,4340.35
  Bottom Layer w40: P3.13@541.41,4340.35 551.02,4340.35 R42.1@650.85,4440.18
Cell13: D17.2 P3.14 Q14.2 R34.2 R44.1 R45.1 R60.1 R156.1 | length 1239.6
  Top Layer w10: R156.1@211,4369 215.5,4369 218,4371.5 218,4379.06 279.29,4440.35 279.29,4447.64 300,4468.35 478.72,4468.35 497.34,4449.73 532.02,4449.73 P3.14@541.41,4440.35 ; D17.2@975.41,4654.29 1028.13,4654.29 R60.1@1030.91,4651.51
  Top Layer w20: R45.1@650.85,4558.43 713.77,4621.35 808.7,4621.35 825.9,4638.55 Q14.2@833.17,4638.55 1017.95,4638.55 R60.1@1030.91,4651.51
  Top Layer w40: P3.14@541.41,4448.99 R45.1@650.85,4558.43
  Bottom Layer w10: R34.2@508.41,4416.97 508.41,4436.7 537.76,4436.7 P3.14@541.41,4440.35
  Bottom Layer w40: P3.14@541.41,4440.35 541.41,4448.99 R44.1@650.85,4558.43
Cell14: D18.2 P3.15 Q15.2 R72.1 R73.1 R74.1 R80.1 R157.1 | length 1279.8
  Top Layer w10: R157.1@181,4369 185.5,4369 188,4371.5 188,4381.06 294.47,4487.53 515.53,4487.53 532.02,4504.02 532.02,4530.96 P3.15@541.41,4540.35
  Top Layer w20: R74.1@650.85,4676.69 714.51,4740.35 809.5,4740.35 825.9,4756.74 Q15.2@833.17,4756.74 1018.22,4756.74 R80.1@1030.91,4769.44
  Top Layer w40: P3.15@541.41,4540.35 541.41,4554.35 650.85,4663.79 R74.1@650.85,4676.69
  Bottom Layer w20: R72.1@508.41,4569.72 537.79,4540.35 P3.15@541.41,4540.35
  Bottom Layer w40: P3.15@541.41,4540.35 541.41,4547.77 650.85,4657.21 R73.1@650.85,4676.69
Cell15: D19.2 P3.16 Q16.2 R72.2 R75.1 R76.1 R82.1 R158.1 | length 1397.3
  Top Layer w10: R158.1@150,4368 154.5,4368 157,4370.5 157,4380.06 287.15,4510.2 484.2,4510.2 500.88,4526.88 500.88,4599.82 P3.16@541.41,4640.35
  Top Layer w20: R75.1@650.85,4794.95 714.25,4858.35 809.3,4858.35 825.9,4874.94 Q16.2@833.17,4874.94 1018.48,4874.94 R82.1@1030.91,4887.38
  Top Layer w40: P3.16@541.41,4640.35 597.41,4696.35 597.41,4725.35 650.85,4778.79 R75.1@650.85,4794.95
  Bottom Layer w20: R72.2@508.41,4616.97 531.79,4640.35 P3.16@541.41,4640.35
  Bottom Layer w40: P3.16@541.41,4640.35 596.94,4695.87 596.94,4724.87 R76.1@650.85,4778.79
Cell16: D11.2 D20.2 D29.2 P3.17 Q17.2 Q32.2 R47.1 R77.1 R78.1 R84.1 R94.2 R159.1 R160.2 R167.1 R176.2 | length 5940
  Top Layer w10: R160.2@82,4327 89.5,4327 94.5,4332 94.5,4339.5 112,4357 112,4364.5 114.5,4367 R159.1@119,4367 123.5,4367 126,4369.5 126,4379.06 276.97,4530.03 460.03,4530.03 469,4539 469,4667.94 P3.17@541.41,4740.35 ; v1(1265.41,4694.35) 1283.54,4694.35 1481.61,4496.27 Q17.2@1538.46,4496.27
  Top Layer w15: R160.2@82,4327 74.5,4327 40.42,4292.92 40.42,2399.58 41,2399 R167.1@104,2399 104,2391.5 115.29,2380.21 115.29,2356.56 Q32.2@119.6,2352.24 119.6,1849.6 R176.2@116,1846
  Top Layer w20: R77.1@650.85,4913.21 705.99,4968.35 775.41,4968.35 812.41,5005.35 R84.1@1030.91,5005.35
  Top Layer w23: D29.2@506.41,4933.69 506.41,4775.35 P3.17@541.41,4740.35 ; P3.17@542.41,4741.35 D20.2@542.41,4933.69 D11.2@590.41,4933.69
  Top Layer w40: P3.17@541.41,4740.35 542.41,4741.35 595.41,4794.35 595.41,4857.76 R77.1@650.85,4913.21
  Bottom Layer w10: R78.1@650.85,4913.21 650.85,4902.9 697.41,4856.35 1250.41,4856.35 1265.41,4841.35 v1(1265.41,4694.35)
  Bottom Layer w23: R47.1@460,4618 460,4621.94 494.38,4656.32 494.38,4693.32 P3.17@541.41,4740.35
  Bottom Layer w40: P3.17@541.41,4740.35 541.41,4862.35 592.27,4913.21 R78.1@650.85,4913.21
CHG: R124.1 U1.45 | length 127.5
  Top Layer w10: U1.45@1747.09,3660.29 R124.1@1874.61,3660.29
DCHG: U1.31 U3.28 | length 1035.8
  Top Layer w10: U1.31@1590.59,3444.74 1590.59,3591.53 v1(1650.41,3651.35) ; U3.28@2141.3,3818.39 2188.06,3818.39 2192.7,3823.03 v2(2195.41,3823.03)
  Bottom Layer w10: v1@1651.41,3652.35 1651.41,3686.35 1925.41,3960.35 2058.1,3960.35 v2(2195.41,3823.03)
DDSG: U1.32 U3.29 | length 1033.1
  Top Layer w10: U1.32@1610.28,3444.74 1610.28,3571.21 v1(1650.41,3611.35) ; U3.29@2141.3,3798.7 2142.21,3797.8 2180.79,3797.8 2181.48,3797.1 v2(2206.48,3797.1)
  Bottom Layer w10: v1(1650.41,3611.35) 1678.41,3639.35 1678.41,3690.35 1931.41,3943.35 2039.04,3943.35 2183.37,3799.02 2204.57,3799.02 v2(2206.48,3797.1)
DSG: D34.1 R131.1 U1.43 | length 297.9
  Top Layer w10: U1.43@1747.09,3620.92 1959.34,3620.92 1966.41,3613.85
  Top Layer w20: D34.1@1966.41,3654.88 1966.41,3613.85 R131.1@1990.91,3589.35
FETOFF: C24.1 D47.1 D48.1 D49.1 R91.2 U1.30 U3.27 | length 3948.1
  Top Layer w10: D49.1@206.47,3833 178.86,3833 173,3827.14 173,3804.19 178.86,3798.34 222.03,3798.34 v1(224.69,3801) 224.69,3755.78 D48.1@231.47,3749 ; v2(375.35,3140.35) 377.26,3142.26 377.26,3161.79 384,3168.53 338.5,3214.03 338.5,3256.56 344.94,3263 351,3263 363.22,3275.22 383.28,3275.22 397,3288.94 v1(397,3556) ; v6(1412.41,3056) 1413.19,3056.79 1413.19,3083.95 1421.98,3092.74 1421.98,3260.35 1429.63,3268 1610.75,3268 1615.83,3273.09 1627.09,3273.09 1631.91,3277.91 1631.91,3331.53 1616.41,3347.03 1616.41,3384.4 1599.59,3401.22 1587.57,3401.22 1571.25,3417.53 1571.25,3444.39 U1.30@1570.91,3444.74 v1@1570.91,3614.84 ; U3.27@2141.3,3838.07 2180.75,3838.07 2191.11,3848.43 2205.81,3848.43 v2(2207.72,3850.35)
  Bottom Layer w10: D47.1@229.69,3801 266,3801 296.43,3770.57 296.43,3687.64 317.15,3666.93 378.07,3666.93 378.47,3666.53 386.75,3666.53 403,3650.28 403,3608.85 397,3602.85 v1(397,3556) ; v2@373,3138 485,3026 1382.41,3026 v6(1412.41,3056) ; v1(1571.41,3615.35) 1571.41,3583.34 C24.1@1587.41,3567.34 ; 1622.41,3576.34 1622.41,3681.35 1919.41,3978.35 2079.72,3978.35 v2(2207.72,3850.35)
  Bottom Layer w20: C24.1@1587.41,3567.34 R91.2@1622.41,3567.34
Fuse: D28.1 Q20.1 R114.2 R173.1 | length 966.2
  Top Layer w20: R173.1@1757.41,3100.35 1801.76,3100.35 Q20.1@1803.17,3101.75 1803.17,3120.6 1832.91,3150.35 1849.41,3133.85 v1(1849.41,3054.35) ; v1@2353.41,3058.35 D28.1@2353.41,3306.23
  Bottom Layer w20: v1(1849.41,3054.35) 1956.51,3054.35 1960.16,3058 2353.76,3058 v1(2355.41,3056.35)
FUSE_AFE: R114.1 U1.38 | length 503.2
  Top Layer w10: U1.38@1747.09,3522.5 1806.26,3522.5 1858.41,3470.35 1888.41,3470.35 1916.62,3442.13 1916.62,3171.06 R114.1@1895.91,3150.35
FUSE_MCU: D28.2 U3.43 | length 199.9
  Top Layer w10: U3.43@2318.47,3601.85 2319.37,3600.95 2319.37,3505.76 2328.41,3496.72 2328.41,3495.35 2334.79,3488.97 2334.79,3435.09 D28.2@2353.41,3416.46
